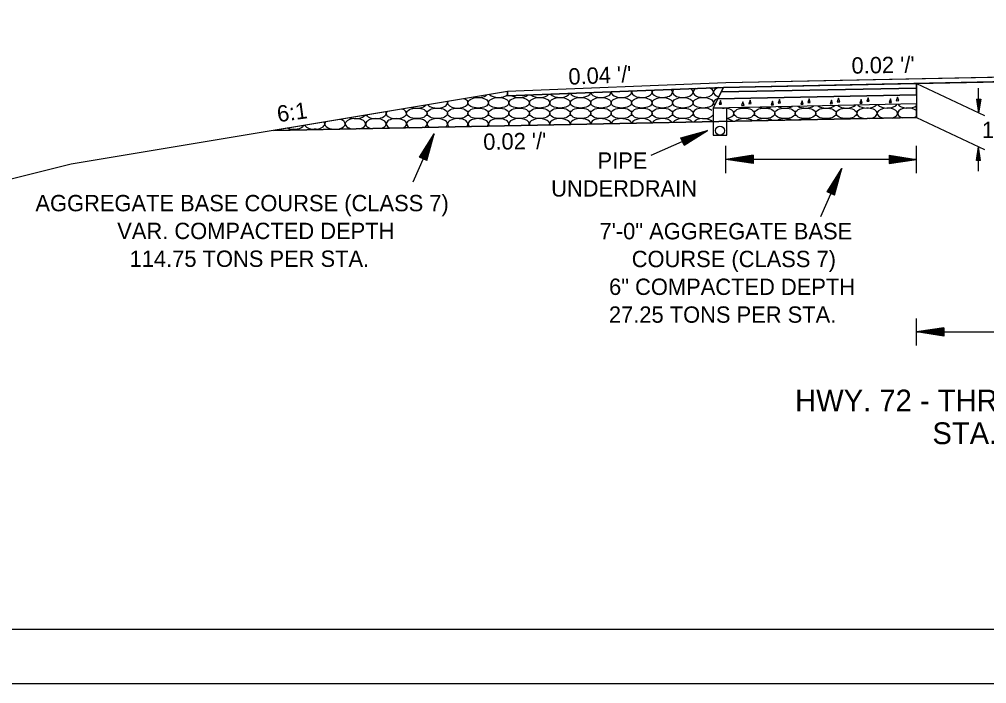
# Model space of a CAD drawing. Extents: x 1371763 to 1372860, y 385599 to 385872.
# Drawn here: x 1372316.68 to 1372352.15, y 385598.59 to 385622.96 of the extents above; entities that cross this region are included whole.
import ezdxf

# ---------------------------------------------------------------- set-up
doc = ezdxf.new("R2010")
doc.units = 0
for name, color, linetype in [('R_Border', 7, 'Continuous'), ('R_Draft', 7, 'Continuous'), ('R_No Plot', 7, 'Continuous')]:
    doc.layers.add(name, color=color, linetype=linetype)

msp = doc.modelspace()

# ---------------------------------------------------------------- linework, layer by layer
at = {"layer": 'R_Border'}
msp.add_line((1372457.298, 385600.577), (1372299.208, 385600.577), dxfattribs=at)
at = {"layer": 'R_Draft'}
for p, q in [((1372360.579, 385620.822), (1372342.495, 385620.46)), ((1372360.579, 385620.989), (1372342.579, 385620.629)), ((1372342.579, 385620.629), (1372334.579, 385620.309)), ((1372342.495, 385620.46), (1372334.579, 385620.144)), ((1372342.495, 385620.46), (1372342.116, 385619.703)), ((1372342.495, 385620.46), (1372342.411, 385620.292)), ((1372349.58, 385620.602), (1372352.068, 385619.43)), ((1372351.855, 385619.53), (1372351.855, 385620.43)), ((1372334.579, 385620.309), (1372318.579, 385617.642)), ((1372334.579, 385620.309), (1372334.579, 385620.144)), ((1372342.411, 385620.292), (1372342.285, 385620.04)), ((1372349.579, 385620.185), (1372342.285, 385620.04)), ((1372342.285, 385620.04), (1372342.116, 385619.703)), ((1372349.579, 385619.852), (1372342.116, 385619.703)), ((1372351.78, 385620.03), (1372351.855, 385619.53)), ((1372351.78, 385620.03), (1372351.93, 385620.03)), ((1372351.792, 385620.03), (1372351.855, 385619.614)), ((1372351.805, 385620.03), (1372351.855, 385619.7)), ((1372351.817, 385620.03), (1372351.855, 385619.783)), ((1372351.83, 385620.03), (1372351.855, 385619.868)), ((1372351.843, 385620.03), (1372351.855, 385619.951)), ((1372351.93, 385620.03), (1372351.855, 385619.53)), ((1372351.879, 385620.03), (1372351.855, 385619.868)), ((1372351.904, 385620.03), (1372351.855, 385619.7)), ((1372351.917, 385620.03), (1372351.855, 385619.614)), ((1372351.892, 385620.03), (1372351.855, 385619.783)), ((1372351.866, 385620.03), (1372351.855, 385619.951)), ((1372349.579, 385619.352), (1372326.011, 385618.881)), ((1372349.579, 385619.352), (1372352.067, 385618.18)), ((1372331.885, 385618.754), (1372331.107, 385616.98)), ((1372331.346, 385617.898), (1372331.885, 385618.754)), ((1372331.621, 385617.778), (1372331.885, 385618.754)), ((1372341.907, 385618.874), (1372339.84, 385617.964)), ((1372340.931, 385618.608), (1372341.907, 385618.874)), ((1372340.941, 385618.585), (1372341.754, 385618.806)), ((1372340.952, 385618.562), (1372341.597, 385618.737)), ((1372340.962, 385618.539), (1372341.444, 385618.67)), ((1372341.022, 385618.403), (1372341.444, 385618.67)), ((1372341.032, 385618.38), (1372341.597, 385618.737)), ((1372341.042, 385618.357), (1372341.754, 385618.806)), ((1372341.052, 385618.334), (1372341.907, 385618.874)), ((1372331.369, 385617.888), (1372331.818, 385618.601)), ((1372331.392, 385617.878), (1372331.749, 385618.443)), ((1372331.574, 385617.798), (1372331.749, 385618.443)), ((1372331.598, 385617.788), (1372331.818, 385618.601)), ((1372341.052, 385618.334), (1372340.931, 385618.608)), ((1372340.972, 385618.516), (1372341.289, 385618.602)), ((1372340.982, 385618.493), (1372341.136, 385618.535)), ((1372341.001, 385618.45), (1372341.136, 385618.535)), ((1372341.011, 385618.427), (1372341.289, 385618.602)), ((1372342.583, 385617.317), (1372342.583, 385618.317)), ((1372349.579, 385617.317), (1372349.579, 385618.317)), ((1372331.415, 385617.868), (1372331.682, 385618.291)), ((1372331.439, 385617.858), (1372331.614, 385618.136)), ((1372331.462, 385617.848), (1372331.547, 385617.983)), ((1372331.505, 385617.829), (1372331.547, 385617.983)), ((1372331.528, 385617.819), (1372331.614, 385618.136)), ((1372331.552, 385617.808), (1372331.682, 385618.291)), ((1372343.583, 385617.967), (1372342.583, 385617.817)), ((1372343.583, 385617.942), (1372342.75, 385617.817)), ((1372343.583, 385617.967), (1372343.583, 385617.667)), ((1372348.579, 385617.967), (1372349.579, 385617.817)), ((1372348.579, 385617.967), (1372348.579, 385617.667)), ((1372348.579, 385617.942), (1372349.412, 385617.817)), ((1372351.779, 385617.78), (1372351.854, 385618.28)), ((1372351.792, 385617.78), (1372351.854, 385618.197)), ((1372351.805, 385617.78), (1372351.854, 385618.111)), ((1372351.817, 385617.78), (1372351.854, 385618.028)), ((1372351.83, 385617.78), (1372351.854, 385617.943)), ((1372351.929, 385617.78), (1372351.854, 385618.28)), ((1372351.854, 385617.38), (1372351.854, 385618.28)), ((1372351.917, 385617.78), (1372351.854, 385618.197)), ((1372351.904, 385617.78), (1372351.854, 385618.111)), ((1372351.892, 385617.78), (1372351.854, 385618.028)), ((1372351.879, 385617.78), (1372351.854, 385617.943)), ((1372318.579, 385617.642), (1372308.878, 385615.217)), ((1372331.621, 385617.778), (1372331.346, 385617.898)), ((1372349.579, 385617.817), (1372342.583, 385617.817)), ((1372343.583, 385617.667), (1372342.583, 385617.817)), ((1372343.583, 385617.692), (1372342.75, 385617.817)), ((1372343.583, 385617.917), (1372342.922, 385617.817)), ((1372343.583, 385617.718), (1372342.922, 385617.817)), ((1372343.583, 385617.892), (1372343.088, 385617.817)), ((1372343.583, 385617.743), (1372343.088, 385617.817)), ((1372343.583, 385617.866), (1372343.258, 385617.817)), ((1372343.583, 385617.768), (1372343.258, 385617.817)), ((1372343.583, 385617.841), (1372343.425, 385617.817)), ((1372343.583, 385617.794), (1372343.425, 385617.817)), ((1372348.579, 385617.917), (1372349.24, 385617.817)), ((1372348.579, 385617.892), (1372349.074, 385617.817)), ((1372348.579, 385617.866), (1372348.904, 385617.817)), ((1372348.579, 385617.841), (1372348.737, 385617.817)), ((1372348.579, 385617.667), (1372349.579, 385617.817)), ((1372348.579, 385617.768), (1372348.904, 385617.817)), ((1372348.579, 385617.718), (1372349.24, 385617.817)), ((1372348.579, 385617.692), (1372349.412, 385617.817)), ((1372348.579, 385617.743), (1372349.074, 385617.817)), ((1372348.579, 385617.794), (1372348.737, 385617.817)), ((1372351.929, 385617.78), (1372351.779, 385617.78)), ((1372351.843, 385617.78), (1372351.854, 385617.859)), ((1372351.866, 385617.78), (1372351.854, 385617.859)), ((1372346.838, 385617.485), (1372346.06, 385615.711)), ((1372346.299, 385616.629), (1372346.838, 385617.485)), ((1372346.322, 385616.619), (1372346.771, 385617.332)), ((1372346.551, 385616.519), (1372346.771, 385617.332)), ((1372346.574, 385616.509), (1372346.838, 385617.485)), ((1372346.345, 385616.609), (1372346.702, 385617.174)), ((1372346.368, 385616.599), (1372346.635, 385617.022)), ((1372346.505, 385616.539), (1372346.635, 385617.022)), ((1372346.528, 385616.529), (1372346.702, 385617.174)), ((1372346.574, 385616.509), (1372346.299, 385616.629)), ((1372346.392, 385616.589), (1372346.567, 385616.867)), ((1372346.415, 385616.579), (1372346.5, 385616.714)), ((1372346.458, 385616.56), (1372346.5, 385616.714)), ((1372346.481, 385616.55), (1372346.567, 385616.867)), ((1372349.579, 385610.987), (1372349.579, 385611.987)), ((1372350.579, 385611.637), (1372349.579, 385611.487)), ((1372350.579, 385611.612), (1372349.746, 385611.487)), ((1372350.579, 385611.586), (1372349.918, 385611.487)), ((1372350.579, 385611.561), (1372350.085, 385611.487)), ((1372350.579, 385611.637), (1372350.579, 385611.337)), ((1372350.579, 385611.337), (1372349.579, 385611.487)), ((1372349.579, 385611.487), (1372371.579, 385611.487)), ((1372350.579, 385611.362), (1372349.746, 385611.487)), ((1372350.579, 385611.387), (1372349.918, 385611.487)), ((1372350.579, 385611.412), (1372350.085, 385611.487)), ((1372350.579, 385611.535), (1372350.254, 385611.487)), ((1372350.579, 385611.438), (1372350.254, 385611.487)), ((1372350.579, 385611.51), (1372350.421, 385611.487)), ((1372350.579, 385611.463), (1372350.421, 385611.487))]:
    msp.add_line(p, q, dxfattribs=at)
for points in [[(1372360.579, 385620.989), (1372342.579, 385620.629), (1372334.579, 385620.309), (1372334.579, 385620.144), (1372342.495, 385620.46), (1372349.58, 385620.602), (1372360.579, 385620.822), (1372371.578, 385620.602), (1372378.664, 385620.46), (1372386.579, 385620.144), (1372386.579, 385620.309), (1372378.579, 385620.629)], [(1372349.579, 385619.352), (1372349.579, 385619.852), (1372342.116, 385619.703), (1372342.285, 385620.04), (1372342.411, 385620.292), (1372342.495, 385620.46), (1372334.579, 385620.144), (1372334.579, 385620.309), (1372326.011, 385618.881)], [(1372349.58, 385620.435), (1372342.411, 385620.292), (1372342.285, 385620.04), (1372349.579, 385620.185)], [(1372349.58, 385620.602), (1372342.495, 385620.46), (1372342.411, 385620.292), (1372349.58, 385620.435)], [(1372349.579, 385619.852), (1372342.116, 385619.703), (1372342.285, 385620.04), (1372349.579, 385620.185)], [(1372342.116, 385619.703), (1372342.116, 385618.705), (1372342.62, 385618.705), (1372342.62, 385619.703)]]:
    msp.add_lwpolyline(points, close=True, dxfattribs=at)
for points in [[(1372349.579, 385620.435), (1372342.411, 385620.292)], [(1372349.58, 385620.602), (1372349.58, 385620.435), (1372349.579, 385620.185), (1372349.579, 385619.852), (1372349.579, 385619.352)], [(1372347.801, 385620.081), (1372347.753, 385619.948), (1372347.841, 385619.952), (1372347.801, 385620.081)], [(1372348.884, 385620.103), (1372348.835, 385619.97), (1372348.923, 385619.973), (1372348.884, 385620.103)], [(1372342.39, 385619.973), (1372342.341, 385619.84), (1372342.429, 385619.844), (1372342.39, 385619.973)], [(1372343.213, 385619.928), (1372343.165, 385619.796), (1372343.253, 385619.799), (1372343.213, 385619.928)], [(1372343.472, 385619.994), (1372343.424, 385619.862), (1372343.512, 385619.865), (1372343.472, 385619.994)], [(1372344.295, 385619.95), (1372344.247, 385619.817), (1372344.335, 385619.821), (1372344.295, 385619.95)], [(1372344.554, 385620.016), (1372344.506, 385619.883), (1372344.594, 385619.887), (1372344.554, 385620.016)], [(1372345.378, 385619.972), (1372345.329, 385619.839), (1372345.417, 385619.843), (1372345.378, 385619.972)], [(1372345.637, 385620.038), (1372345.588, 385619.905), (1372345.676, 385619.908), (1372345.637, 385620.038)], [(1372346.46, 385619.993), (1372346.412, 385619.861), (1372346.5, 385619.864), (1372346.46, 385619.993)], [(1372346.719, 385620.059), (1372346.671, 385619.927), (1372346.759, 385619.93), (1372346.719, 385620.059)], [(1372347.542, 385620.015), (1372347.494, 385619.882), (1372347.582, 385619.886), (1372347.542, 385620.015)], [(1372348.625, 385620.037), (1372348.576, 385619.904), (1372348.664, 385619.907), (1372348.625, 385620.037)]]:
    msp.add_lwpolyline(points, dxfattribs=at)
msp.add_circle((1372342.368, 385618.872), 0.167, dxfattribs=at)
for centre, start_param, end_param in [((1372341.756, 385620.284), 2.362051, 6.299349), ((1372341.756, 385620.284), 0.016164, 0.933643), ((1372342.506, 385620.284), 2.07641, 4.19881), ((1372333.503, 385620.284), 4.309567, 5.737915), ((1372334.253, 385620.284), 3.596378, 5.76472), ((1372335.004, 385620.284), 3.900097, 5.678782), ((1372335.754, 385620.284), 3.714715, 5.864164), ((1372336.504, 385620.284), 3.546511, 6.032368), ((1372337.255, 385620.284), 3.387522, 6.191357), ((1372338.005, 385620.284), 3.232772, 6.346107), ((1372338.755, 385620.284), 3.078363, 6.500516), ((1372339.505, 385620.284), 2.920476, 6.658403), ((1372340.256, 385620.284), 2.754432, 6.824447), ((1372341.006, 385620.284), 2.573058, 7.005822), ((1372331.252, 385619.895), 4.214256, 5.833227), ((1372332.003, 385619.895), 3.5302, 6.517282), ((1372332.753, 385619.895), 2.887829, 6.459274), ((1372332.753, 385619.895), 0.176089, 0.876468), ((1372341.756, 385619.507), 0.574878, 5.999831), ((1372342.506, 385619.895), 2.178621, 3.597806), ((1372342.506, 385619.895), 4.429061, 5.072915), ((1372343.257, 385619.895), 4.23834, 5.263637), ((1372344.007, 385619.895), 4.097996, 5.40398), ((1372344.757, 385619.895), 3.97981, 5.522166), ((1372345.508, 385619.895), 3.874575, 5.627402), ((1372346.258, 385619.895), 3.777879, 5.724097), ((1372347.008, 385619.895), 3.687188, 5.814789), ((1372347.758, 385619.895), 3.600864, 5.901112), ((1372348.509, 385619.895), 3.517762, 5.984215), ((1372349.259, 385619.507), 0.546766, 4.154346), ((1372349.259, 385619.895), 3.437022, 5.73642), ((1372329.002, 385619.507), 4.126933, 5.920549), ((1372329.752, 385619.507), 3.46436, 6.583122), ((1372330.502, 385619.507), 2.807846, 6.741256), ((1372330.502, 385619.507), 0.458071, 0.956451), ((1372342.506, 385619.507), 5.019035, 7.547335), ((1372347.758, 385619.507), 4.943194, 10.841967), ((1372348.509, 385619.507), 5.191799, 10.593363), ((1372349.259, 385619.507), 5.34763, 5.73642), ((1372326.751, 385619.118), 4.045333, 6.00215), ((1372327.501, 385619.118), 3.398569, 6.473406), ((1372327.501, 385619.118), 0.190221, 0.365728), ((1372328.251, 385619.118), 2.722715, 4.607551), ((1372328.251, 385619.118), 4.894426, 7.039169), ((1372328.251, 385619.118), 0.755983, 1.041582), ((1372329.002, 385619.118), 5.172304, 9.97112), ((1372329.002, 385619.118), 3.687935, 4.329672), ((1372329.752, 385619.118), 5.332975, 9.762374), ((1372329.752, 385619.118), 3.479188, 4.169002), ((1372330.502, 385619.118), 0.057347, 4.04073), ((1372330.502, 385619.118), 5.461247, 6.340532), ((1372331.252, 385619.118), 0.254169, 3.929339), ((1372331.252, 385619.118), 5.572638, 6.537354), ((1372332.003, 385619.118), 0.457389, 3.828496), ((1372332.003, 385619.118), 5.673481, 6.740574), ((1372332.753, 385619.118), 0.6778, 3.734854), ((1372332.753, 385619.118), 5.767122, 6.960986), ((1372333.503, 385619.118), 0.937029, 3.646372), ((1372333.503, 385619.118), 5.855605, 7.220215), ((1372334.253, 385619.118), 0.518465, 3.561676), ((1372334.253, 385619.118), 5.940301, 6.80165), ((1372335.004, 385619.118), 6.022204, 9.762957), ((1372335.754, 385619.118), 6.102081, 9.68308), ((1372336.504, 385619.118), 6.180555, 9.604607), ((1372337.255, 385619.118), 6.25816, 9.527002), ((1372338.005, 385619.118), 0.052197, 3.166594), ((1372338.755, 385619.118), 0.129501, 3.08929), ((1372339.505, 385619.118), 0.207354, 3.011437), ((1372340.256, 385619.118), 0.286258, 2.932533), ((1372341.006, 385619.118), 0.366772, 2.852019), ((1372341.756, 385619.118), 0.449562, 2.769228), ((1372342.506, 385619.118), 0.535464, 1.26415), ((1372343.257, 385619.118), 0.625581, 2.59321), ((1372344.007, 385619.118), 0.721479, 2.497312), ((1372344.757, 385619.118), 0.825557, 2.393234), ((1372345.508, 385619.118), 0.941922, 2.276869), ((1372346.258, 385619.118), 1.078921, 2.13987), ((1372347.008, 385619.118), 1.260486, 1.958305), ((1372326.001, 385618.729), 0.928871, 1.133787), ((1372326.751, 385618.729), 1.063036, 2.155755), ((1372327.501, 385618.729), 1.237391, 1.9814)]:
    msp.add_ellipse(centre, major_axis=(0.375, 0), ratio=0.517889, start_param=start_param, end_param=end_param, dxfattribs=at)
for centre in [(1372333.503, 385619.895), (1372334.253, 385619.895), (1372335.004, 385619.895), (1372335.754, 385619.895), (1372336.504, 385619.895), (1372337.255, 385619.895), (1372338.005, 385619.895), (1372338.755, 385619.895), (1372339.505, 385619.895), (1372340.256, 385619.895), (1372341.006, 385619.895), (1372341.756, 385619.895), (1372331.252, 385619.507), (1372332.003, 385619.507), (1372332.753, 385619.507), (1372333.503, 385619.507), (1372334.253, 385619.507), (1372335.004, 385619.507), (1372335.754, 385619.507), (1372336.504, 385619.507), (1372337.255, 385619.507), (1372338.005, 385619.507), (1372338.755, 385619.507), (1372339.505, 385619.507), (1372340.256, 385619.507), (1372341.006, 385619.507), (1372343.257, 385619.507), (1372344.007, 385619.507), (1372344.757, 385619.507), (1372345.508, 385619.507), (1372346.258, 385619.507), (1372347.008, 385619.507)]:
    msp.add_ellipse(centre, major_axis=(0.375, 0), ratio=0.517889, dxfattribs=at)
at = {"layer": 'R_No Plot'}
msp.add_line((1372293.007, 385598.587), (1372459.674, 385598.587), dxfattribs=at)
for points in [[(1372293.004, 385705.254), (1372459.674, 385705.254), (1372459.674, 385598.585), (1372293.004, 385598.585)], [(1372416.168, 385703.307), (1372425.978, 385703.307), (1372425.978, 385698.367), (1372434.034, 385698.367), (1372445.634, 385698.367), (1372445.634, 385682.032), (1372457.238, 385682.032), (1372457.298, 385600.577), (1372299.208, 385600.577), (1372299.208, 385703.307)]]:
    msp.add_lwpolyline(points, close=True, dxfattribs=at)

# ---------------------------------------------------------------- texts
at = {"layer": 'R_Draft'}
for s, rotation, p in [("0.02 '/'", 0.9853, (1372347.199, 385620.96)), ("0.04 '/'", 2.3777, (1372336.823, 385620.555)), ('6:1', 7.7154, (1372326.167, 385619.181)), ("0.02 '/'", 0.9853, (1372333.693, 385618.165)), ('PIPE', 0, (1372337.881, 385617.474)), ('UNDERDRAIN', 0, (1372336.178, 385616.454)), ('AGGREGATE BASE COURSE (CLASS 7)', 0, (1372317.266, 385615.914)), ('VAR. COMPACTED DEPTH', 0, (1372320.266, 385614.894)), ('7\'-0" AGGREGATE BASE ', 0, (1372337.952, 385614.885)), ('114.75 TONS PER STA.', 0, (1372320.72, 385613.874)), ('COURSE (CLASS 7)', 0, (1372339.133, 385613.865)), ('6" COMPACTED DEPTH', 0, (1372338.302, 385612.845)), ('27.25 TONS PER STA.', 0, (1372338.297, 385611.825))]:
    msp.add_text(s, height=0.6, rotation=rotation, dxfattribs=at).set_placement(p)
for s, height, p in [('15" NOTCH', 0.6, (1372351.975, 385618.6)), ('HWY. 72 - THREE LANE NOTCH AND WIDEN SECTION', 0.8, (1372345.124, 385608.571)), ('STA. 102+65.00 TO STA. 109+88.53', 0.8, (1372350.16, 385607.371))]:
    msp.add_text(s, height=height, dxfattribs=at).set_placement(p)

doc.saveas('drawing.dxf')
